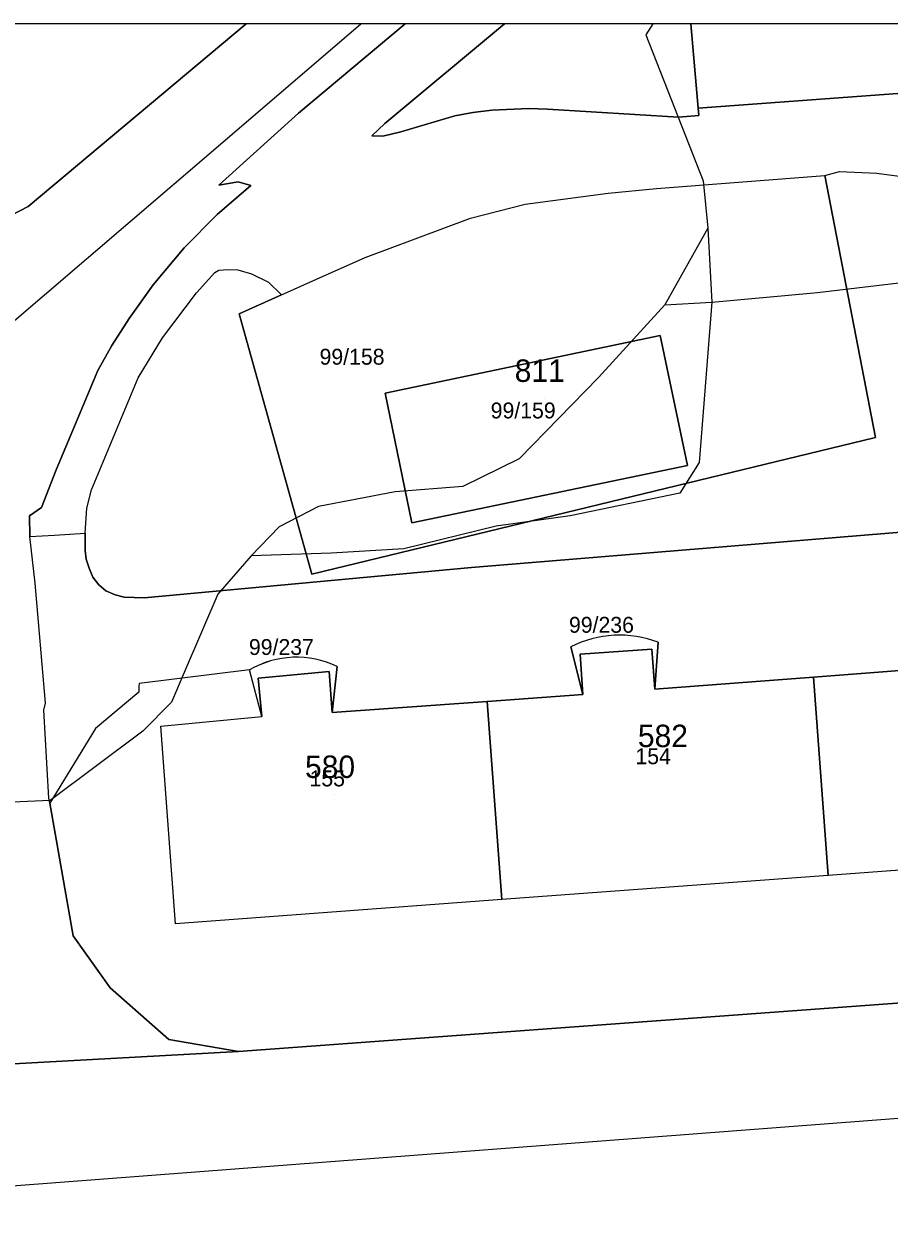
# Model space of a CAD drawing. Extents: x -873642 to -872917, y -1012962 to -1012567.
# Drawn here: x -873481.3 to -873435, y -1012631 to -1012567.5 of the extents above; entities that cross this region are included whole.
import ezdxf

# ---------------------------------------------------------------- set-up
doc = ezdxf.new("R2010")
doc.units = 0
for name, color, linetype in [('adresni_misto', 7, 'Continuous'), ('cisla_parcelni_kn', 7, 'Continuous'), ('cislo_domovni', 7, 'Continuous'), ('osy_ulic', 7, 'Continuous'), ('parcely_kn', 7, 'Continuous'), ('stavebni_objekty_bydleni', 7, 'Continuous'), ('TRASY - zamereno', 7, 'Continuous')]:
    doc.layers.add(name, color=color, linetype=linetype)

msp = doc.modelspace()

# ---------------------------------------------------------------- linework, layer by layer
at = {"layer": 'adresni_misto'}
for p, q in [((-873453.46, -1012587.56), (-873453.46, -1012587.56)), ((-873446.87, -1012607.1), (-873446.87, -1012607.1)), ((-873464.68, -1012608.75), (-873464.68, -1012608.75))]:
    msp.add_line(p, q, dxfattribs=at)
at = {"layer": 'osy_ulic'}
for points in [[(-873484.82, -1012585.93), (-873471.05, -1012574.15), (-873463.295, -1012567.5)], [(-872916.927, -1012586.659), (-872957.62, -1012590.24), (-872977.73, -1012591.46), (-872994.83, -1012592.51), (-873031.96, -1012595.34), (-873059.56, -1012597.3), (-873096.52, -1012600.28), (-873281.07, -1012614.36), (-873481.95, -1012629.68)]]:
    msp.add_lwpolyline(points, dxfattribs=at)
at = {"layer": 'parcely_kn'}
for p, q in [((-873469.424, -1012567.5), (-873497.388, -1012567.5)), ((-873469.424, -1012567.5), (-873497.388, -1012567.5)), ((-873460.925, -1012567.5), (-873469.424, -1012567.5)), ((-873460.925, -1012567.5), (-873469.424, -1012567.5)), ((-873455.607, -1012567.5), (-873460.925, -1012567.5)), ((-873455.607, -1012567.5), (-873460.925, -1012567.5)), ((-873445.635, -1012567.5), (-873455.607, -1012567.5)), ((-873445.635, -1012567.5), (-873455.607, -1012567.5)), ((-873427.436, -1012567.5), (-873445.635, -1012567.5)), ((-873427.436, -1012567.5), (-873445.635, -1012567.5))]:
    msp.add_line(p, q, dxfattribs=at)
for points in [[(-873497.388, -1012567.5), (-873487.83, -1012577.76), (-873484.77, -1012578.86), (-873482.9, -1012578.2), (-873481.1, -1012577.28), (-873469.424, -1012567.5)], [(-873497.388, -1012567.5), (-873487.83, -1012577.76), (-873484.77, -1012578.86), (-873482.9, -1012578.2), (-873481.1, -1012577.28), (-873469.424, -1012567.5)], [(-873491.33, -1012623.66), (-873469.84, -1012622.48), (-873473.56, -1012621.85), (-873476.71, -1012619.07), (-873478.69, -1012616.29), (-873479.94, -1012609.19), (-873479.99, -1012608.93), (-873480.25, -1012604.22), (-873480.17, -1012603.85), (-873480.72, -1012597.42), (-873481, -1012594.94), (-873481.03, -1012593.83), (-873480.38, -1012593.38), (-873479.6, -1012591.37), (-873478.7, -1012589.24), (-873477.36, -1012586.05), (-873476.61, -1012584.71), (-873475.69, -1012583.26), (-873474.41, -1012581.46), (-873472.75, -1012579.49), (-873470.98, -1012577.7), (-873470.59, -1012577.36), (-873469.18, -1012576.16), (-873469.86, -1012575.96), (-873470.89, -1012576.13), (-873466.63, -1012572.29), (-873463.77, -1012569.89), (-873460.925, -1012567.5)], [(-873491.33, -1012623.66), (-873469.84, -1012622.48), (-873473.56, -1012621.85), (-873476.71, -1012619.07), (-873478.69, -1012616.29), (-873479.94, -1012609.19), (-873479.99, -1012608.93), (-873480.25, -1012604.22), (-873480.17, -1012603.85), (-873480.72, -1012597.42), (-873481, -1012594.94), (-873481.03, -1012593.83), (-873480.38, -1012593.38), (-873479.6, -1012591.37), (-873478.7, -1012589.24), (-873477.36, -1012586.05), (-873476.61, -1012584.71), (-873475.69, -1012583.26), (-873474.41, -1012581.46), (-873472.75, -1012579.49), (-873470.98, -1012577.7), (-873470.59, -1012577.36), (-873469.18, -1012576.16), (-873469.86, -1012575.96), (-873470.89, -1012576.13), (-873466.63, -1012572.29), (-873463.77, -1012569.89), (-873460.925, -1012567.5)], [(-873469.424, -1012567.5), (-873481.1, -1012577.28), (-873482.9, -1012578.2)], [(-873469.424, -1012567.5), (-873481.1, -1012577.28), (-873482.9, -1012578.2)], [(-873460.925, -1012567.5), (-873463.77, -1012569.89), (-873466.63, -1012572.29), (-873470.89, -1012576.13), (-873469.86, -1012575.96), (-873469.18, -1012576.16), (-873470.59, -1012577.36), (-873470.98, -1012577.7), (-873472.75, -1012579.49), (-873474.41, -1012581.46), (-873475.69, -1012583.26), (-873476.61, -1012584.71), (-873477.36, -1012586.05), (-873478.7, -1012589.24), (-873479.6, -1012591.37), (-873480.38, -1012593.38), (-873481.03, -1012593.83), (-873481, -1012594.94), (-873479.68, -1012594.86), (-873478.04, -1012594.75), (-873477.96, -1012593.41), (-873477.71, -1012592.43), (-873475.2, -1012586.45), (-873473.91, -1012584.31), (-873472.09, -1012581.89), (-873471.1, -1012580.8), (-873470.89, -1012580.68), (-873470.4, -1012580.64), (-873469.88, -1012580.67), (-873469.15, -1012580.88), (-873468.24, -1012581.32), (-873467.53, -1012582), (-873465.67, -1012581.17), (-873463.07, -1012580), (-873457.43, -1012577.9), (-873454.51, -1012577.15), (-873450.06, -1012576.56), (-873447.47, -1012576.31), (-873438.46, -1012575.62), (-873437.69, -1012575.4), (-873435.68, -1012575.49), (-873433.69, -1012575.76)], [(-873460.925, -1012567.5), (-873463.77, -1012569.89), (-873466.63, -1012572.29), (-873470.89, -1012576.13), (-873469.86, -1012575.96), (-873469.18, -1012576.16), (-873470.59, -1012577.36), (-873470.98, -1012577.7), (-873472.75, -1012579.49), (-873474.41, -1012581.46), (-873475.69, -1012583.26), (-873476.61, -1012584.71), (-873477.36, -1012586.05), (-873478.7, -1012589.24), (-873479.6, -1012591.37), (-873480.38, -1012593.38), (-873481.03, -1012593.83), (-873481, -1012594.94), (-873479.68, -1012594.86), (-873478.04, -1012594.75), (-873477.96, -1012593.41), (-873477.71, -1012592.43), (-873475.2, -1012586.45), (-873473.91, -1012584.31), (-873472.09, -1012581.89), (-873471.1, -1012580.8), (-873470.89, -1012580.68), (-873470.4, -1012580.64), (-873469.88, -1012580.67), (-873469.15, -1012580.88), (-873468.24, -1012581.32), (-873467.53, -1012582), (-873465.67, -1012581.17), (-873463.07, -1012580), (-873457.43, -1012577.9), (-873454.51, -1012577.15), (-873450.06, -1012576.56), (-873447.47, -1012576.31), (-873438.46, -1012575.62), (-873437.69, -1012575.4), (-873435.68, -1012575.49), (-873433.69, -1012575.76)], [(-873427.436, -1012567.5), (-873427.29, -1012570.69), (-873445.24, -1012572.02), (-873445.21, -1012572.41), (-873446.29, -1012572.49), (-873453.3, -1012572.07), (-873454.3, -1012572.03), (-873456.29, -1012572.12), (-873457.3, -1012572.25), (-873458.26, -1012572.43), (-873461.15, -1012573.28), (-873462.12, -1012573.52), (-873462.71, -1012573.49), (-873462.01, -1012572.83), (-873455.607, -1012567.5)], [(-873455.607, -1012567.5), (-873462.01, -1012572.83), (-873462.71, -1012573.49), (-873462.12, -1012573.52), (-873461.15, -1012573.28), (-873458.26, -1012572.43), (-873457.3, -1012572.25), (-873456.29, -1012572.12), (-873454.3, -1012572.03), (-873453.3, -1012572.07), (-873446.29, -1012572.49), (-873445.21, -1012572.41), (-873445.24, -1012572.02), (-873445.635, -1012567.5)], [(-873427.436, -1012567.5), (-873427.29, -1012570.69), (-873445.24, -1012572.02), (-873445.21, -1012572.41), (-873446.29, -1012572.49), (-873453.3, -1012572.07), (-873454.3, -1012572.03), (-873456.29, -1012572.12), (-873457.3, -1012572.25), (-873458.26, -1012572.43), (-873461.15, -1012573.28), (-873462.12, -1012573.52), (-873462.71, -1012573.49), (-873462.01, -1012572.83), (-873455.607, -1012567.5)], [(-873455.607, -1012567.5), (-873462.01, -1012572.83), (-873462.71, -1012573.49), (-873462.12, -1012573.52), (-873461.15, -1012573.28), (-873458.26, -1012572.43), (-873457.3, -1012572.25), (-873456.29, -1012572.12), (-873454.3, -1012572.03), (-873453.3, -1012572.07), (-873446.29, -1012572.49), (-873445.21, -1012572.41), (-873445.24, -1012572.02), (-873445.635, -1012567.5)], [(-873445.635, -1012567.5), (-873445.24, -1012572.02), (-873427.29, -1012570.69), (-873427.436, -1012567.5)], [(-873445.635, -1012567.5), (-873445.24, -1012572.02), (-873427.29, -1012570.69), (-873427.436, -1012567.5)], [(-873430.92, -1012594.41), (-873457.37, -1012596.59), (-873474.88, -1012598.21), (-873475.95, -1012598.18), (-873476.43, -1012598.05), (-873476.93, -1012597.83), (-873477.31, -1012597.51), (-873477.63, -1012597.1), (-873477.83, -1012596.62), (-873477.99, -1012596.15), (-873478.04, -1012595.68), (-873478.04, -1012594.75), (-873477.96, -1012593.41), (-873477.71, -1012592.43), (-873475.2, -1012586.45), (-873473.91, -1012584.31), (-873472.09, -1012581.89), (-873471.1, -1012580.8), (-873470.89, -1012580.68), (-873470.4, -1012580.64), (-873469.88, -1012580.67), (-873469.15, -1012580.88), (-873468.24, -1012581.32), (-873467.53, -1012582), (-873469.8, -1012583.02), (-873465.92, -1012596.95), (-873435.75, -1012589.63), (-873438.46, -1012575.62), (-873437.69, -1012575.4), (-873435.68, -1012575.49), (-873433.69, -1012575.76)], [(-873430.92, -1012594.41), (-873457.37, -1012596.59), (-873474.88, -1012598.21), (-873475.95, -1012598.18), (-873476.43, -1012598.05), (-873476.93, -1012597.83), (-873477.31, -1012597.51), (-873477.63, -1012597.1), (-873477.83, -1012596.62), (-873477.99, -1012596.15), (-873478.04, -1012595.68), (-873478.04, -1012594.75), (-873477.96, -1012593.41), (-873477.71, -1012592.43), (-873475.2, -1012586.45), (-873473.91, -1012584.31), (-873472.09, -1012581.89), (-873471.1, -1012580.8), (-873470.89, -1012580.68), (-873470.4, -1012580.64), (-873469.88, -1012580.67), (-873469.15, -1012580.88), (-873468.24, -1012581.32), (-873467.53, -1012582), (-873469.8, -1012583.02), (-873465.92, -1012596.95), (-873435.75, -1012589.63), (-873438.46, -1012575.62), (-873437.69, -1012575.4), (-873435.68, -1012575.49), (-873433.69, -1012575.76)], [(-873469.25, -1012602.07), (-873475.15, -1012602.79), (-873475.18, -1012602.94), (-873475.17, -1012603.26), (-873477.49, -1012605.2), (-873479.94, -1012609.19), (-873479.99, -1012608.93), (-873480.25, -1012604.22), (-873480.17, -1012603.85), (-873480.72, -1012597.42), (-873481, -1012594.94), (-873479.68, -1012594.86), (-873478.04, -1012594.75), (-873478.04, -1012595.68), (-873477.99, -1012596.15), (-873477.83, -1012596.62), (-873477.63, -1012597.1), (-873477.31, -1012597.51), (-873476.93, -1012597.83), (-873476.43, -1012598.05), (-873475.95, -1012598.18), (-873474.88, -1012598.21), (-873457.37, -1012596.59), (-873430.92, -1012594.41)], [(-873469.25, -1012602.07), (-873475.15, -1012602.79), (-873475.18, -1012602.94), (-873475.17, -1012603.26), (-873477.49, -1012605.2), (-873479.94, -1012609.19), (-873479.99, -1012608.93), (-873480.25, -1012604.22), (-873480.17, -1012603.85), (-873480.72, -1012597.42), (-873481, -1012594.94), (-873479.68, -1012594.86), (-873478.04, -1012594.75), (-873478.04, -1012595.68), (-873477.99, -1012596.15), (-873477.83, -1012596.62), (-873477.63, -1012597.1), (-873477.31, -1012597.51), (-873476.93, -1012597.83), (-873476.43, -1012598.05), (-873475.95, -1012598.18), (-873474.88, -1012598.21), (-873457.37, -1012596.59), (-873430.92, -1012594.41)], [(-873143.44, -1012597.91), (-873216.55, -1012603.73), (-873279.94, -1012608.27), (-873348.3, -1012613.15), (-873406.66, -1012617.85), (-873469.84, -1012622.48), (-873491.33, -1012623.66), (-873566.46, -1012629.92), (-873583.11, -1012630.93), (-873584.28, -1012631.65), (-873606.27, -1012634.41), (-873608.98, -1012633.05), (-873615.37, -1012633.09), (-873642.294, -1012633.957)], [(-873431.45, -1012599.47), (-873430.98, -1012601.84), (-873439.07, -1012602.45), (-873447.57, -1012603.1), (-873447.38, -1012600.59)], [(-873431.45, -1012599.47), (-873430.98, -1012601.84), (-873439.07, -1012602.45), (-873447.57, -1012603.1), (-873447.38, -1012600.59)], [(-873407.04, -1012610.98), (-873418.47, -1012611.57), (-873418.89, -1012601.06), (-873421.55, -1012601.17), (-873420.8, -1012611.77), (-873438.29, -1012613.07), (-873455.75, -1012614.36), (-873473.21, -1012615.66), (-873473.99, -1012605.07), (-873468.6, -1012604.57), (-873469.25, -1012602.07), (-873475.15, -1012602.79), (-873475.18, -1012602.94), (-873475.17, -1012603.26), (-873477.49, -1012605.2), (-873479.94, -1012609.19), (-873478.69, -1012616.29), (-873476.71, -1012619.07), (-873473.56, -1012621.85), (-873469.84, -1012622.48), (-873406.66, -1012617.85)], [(-873407.04, -1012610.98), (-873418.47, -1012611.57), (-873418.89, -1012601.06), (-873421.55, -1012601.17), (-873420.8, -1012611.77), (-873438.29, -1012613.07), (-873455.75, -1012614.36), (-873473.21, -1012615.66), (-873473.99, -1012605.07), (-873468.6, -1012604.57), (-873469.25, -1012602.07), (-873475.15, -1012602.79), (-873475.18, -1012602.94), (-873475.17, -1012603.26), (-873477.49, -1012605.2), (-873479.94, -1012609.19), (-873478.69, -1012616.29), (-873476.71, -1012619.07), (-873473.56, -1012621.85), (-873469.84, -1012622.48), (-873406.66, -1012617.85)], [(-873452.06, -1012600.84), (-873451.41, -1012603.38), (-873456.54, -1012603.75), (-873464.82, -1012604.35), (-873464.56, -1012601.89)], [(-873452.06, -1012600.84), (-873451.41, -1012603.38), (-873456.54, -1012603.75), (-873464.82, -1012604.35), (-873464.56, -1012601.89)], [(-873451.56, -1012601.23), (-873451.41, -1012603.38), (-873452.06, -1012600.84)], [(-873451.56, -1012601.23), (-873451.41, -1012603.38), (-873452.06, -1012600.84)], [(-873447.38, -1012600.59), (-873447.57, -1012603.1), (-873447.73, -1012600.96), (-873451.56, -1012601.23)], [(-873447.38, -1012600.59), (-873447.57, -1012603.1), (-873447.73, -1012600.96), (-873451.56, -1012601.23)], [(-873468.79, -1012602.51), (-873468.6, -1012604.57), (-873469.25, -1012602.07)], [(-873468.79, -1012602.51), (-873468.6, -1012604.57), (-873469.25, -1012602.07)], [(-873464.56, -1012601.89), (-873464.82, -1012604.35), (-873464.98, -1012602.15), (-873468.79, -1012602.51)], [(-873464.56, -1012601.89), (-873464.82, -1012604.35), (-873464.98, -1012602.15), (-873468.79, -1012602.51)]]:
    msp.add_lwpolyline(points, dxfattribs=at)
for points in [[(-873463.07, -1012580), (-873457.43, -1012577.9), (-873454.51, -1012577.15), (-873450.06, -1012576.56), (-873447.47, -1012576.31), (-873438.46, -1012575.62), (-873435.75, -1012589.63), (-873465.92, -1012596.95), (-873469.8, -1012583.02), (-873467.53, -1012582), (-873465.67, -1012581.17)], [(-873463.07, -1012580), (-873457.43, -1012577.9), (-873454.51, -1012577.15), (-873450.06, -1012576.56), (-873447.47, -1012576.31), (-873438.46, -1012575.62), (-873435.75, -1012589.63), (-873465.92, -1012596.95), (-873469.8, -1012583.02), (-873467.53, -1012582), (-873465.67, -1012581.17)], [(-873462, -1012587.26), (-873447.27, -1012584.18), (-873445.82, -1012591.14), (-873460.56, -1012594.2)], [(-873445.82, -1012591.14), (-873447.27, -1012584.18), (-873462, -1012587.26), (-873460.56, -1012594.2)], [(-873462, -1012587.26), (-873447.27, -1012584.18), (-873445.82, -1012591.14), (-873460.56, -1012594.2)], [(-873445.82, -1012591.14), (-873447.27, -1012584.18), (-873462, -1012587.26), (-873460.56, -1012594.2)], [(-873439.07, -1012602.45), (-873430.98, -1012601.84), (-873431.13, -1012599.78), (-873427.15, -1012599.48), (-873427, -1012601.56), (-873421.55, -1012601.17), (-873420.8, -1012611.77), (-873438.29, -1012613.07)], [(-873439.07, -1012602.45), (-873430.98, -1012601.84), (-873431.13, -1012599.78), (-873427.15, -1012599.48), (-873427, -1012601.56), (-873421.55, -1012601.17), (-873420.8, -1012611.77), (-873438.29, -1012613.07)], [(-873456.54, -1012603.75), (-873451.41, -1012603.38), (-873451.56, -1012601.23), (-873447.73, -1012600.96), (-873447.57, -1012603.1), (-873439.07, -1012602.45), (-873438.29, -1012613.07), (-873455.75, -1012614.36)], [(-873456.54, -1012603.75), (-873451.41, -1012603.38), (-873451.56, -1012601.23), (-873447.73, -1012600.96), (-873447.57, -1012603.1), (-873439.07, -1012602.45), (-873438.29, -1012613.07), (-873455.75, -1012614.36)], [(-873464.82, -1012604.35), (-873456.54, -1012603.75), (-873455.75, -1012614.36), (-873473.21, -1012615.66), (-873473.99, -1012605.07), (-873468.6, -1012604.57), (-873468.79, -1012602.51), (-873464.98, -1012602.15)], [(-873464.82, -1012604.35), (-873456.54, -1012603.75), (-873455.75, -1012614.36), (-873473.21, -1012615.66), (-873473.99, -1012605.07), (-873468.6, -1012604.57), (-873468.79, -1012602.51), (-873464.98, -1012602.15)]]:
    msp.add_lwpolyline(points, close=True, dxfattribs=at)
for centre, radius, start, end in [((-873449.44, -1012605.957), 5.749, 69.00091, 117.11462), ((-873449.44, -1012605.957), 5.748, 69.00081, 117.11472), ((-873449.44, -1012605.957), 5.749, 69.00091, 117.11462), ((-873449.44, -1012605.957), 5.748, 69.00081, 117.11472), ((-873466.736, -1012606.388), 4.996, 64.18303, 120.21278), ((-873466.736, -1012606.387), 4.996, 64.18244, 120.21337), ((-873466.736, -1012606.388), 4.996, 64.18303, 120.21278), ((-873466.736, -1012606.387), 4.996, 64.18244, 120.21337)]:
    msp.add_arc(centre, radius, start, end, dxfattribs=at)
at = {"layer": 'stavebni_objekty_bydleni'}
msp.add_line((-873427.436, -1012567.5), (-873445.635, -1012567.5), dxfattribs=at)
msp.add_lwpolyline([(-873445.635, -1012567.5), (-873445.24, -1012572.02), (-873427.29, -1012570.69), (-873427.436, -1012567.5)], dxfattribs=at)
for points in [[(-873462, -1012587.26), (-873447.27, -1012584.18), (-873445.82, -1012591.14), (-873460.56, -1012594.2)], [(-873438.29, -1012613.07), (-873439.07, -1012602.45), (-873430.98, -1012601.84), (-873431.13, -1012599.78), (-873427.15, -1012599.48), (-873427, -1012601.56), (-873421.55, -1012601.17), (-873420.8, -1012611.77)], [(-873455.75, -1012614.36), (-873456.54, -1012603.75), (-873451.41, -1012603.38), (-873451.56, -1012601.23), (-873447.73, -1012600.96), (-873447.57, -1012603.1), (-873439.07, -1012602.45), (-873438.29, -1012613.07)], [(-873473.21, -1012615.66), (-873473.99, -1012605.07), (-873468.6, -1012604.57), (-873468.79, -1012602.51), (-873464.98, -1012602.15), (-873464.82, -1012604.35), (-873456.54, -1012603.75), (-873455.75, -1012614.36)]]:
    msp.add_lwpolyline(points, close=True, dxfattribs=at)
at = {"layer": 'TRASY - zamereno'}
for p, q in [((-873447.674, -1012567.5), (-873448.04, -1012568.09)), ((-873448.04, -1012568.09), (-873444.98, -1012575.91)), ((-873444.98, -1012575.91), (-873444.73, -1012578.44)), ((-873444.73, -1012578.44), (-873447.03, -1012582.54)), ((-873444.73, -1012578.44), (-873444.51, -1012582.4)), ((-873438.86, -1012581.88), (-873432.13, -1012581.07)), ((-873444.51, -1012582.4), (-873438.86, -1012581.88)), ((-873447.03, -1012582.54), (-873450.57, -1012586.43)), ((-873447.03, -1012582.54), (-873444.51, -1012582.4)), ((-873444.51, -1012582.4), (-873445.2, -1012590.97)), ((-873450.57, -1012586.43), (-873454.82, -1012590.78)), ((-873454.82, -1012590.78), (-873457.84, -1012592.26)), ((-873445.2, -1012590.97), (-873446.23, -1012592.62)), ((-873457.84, -1012592.26), (-873461.45, -1012592.55)), ((-873461.45, -1012592.55), (-873465.56, -1012593.32)), ((-873446.23, -1012592.62), (-873452.09, -1012593.82)), ((-873465.56, -1012593.32), (-873467.67, -1012594.42)), ((-873452.09, -1012593.82), (-873456.06, -1012594.38)), ((-873467.67, -1012594.42), (-873469.17, -1012595.96)), ((-873456.06, -1012594.38), (-873460.99, -1012595.6)), ((-873469.17, -1012595.96), (-873470.94, -1012598.02)), ((-873464.88, -1012595.83), (-873469.17, -1012595.96)), ((-873460.99, -1012595.6), (-873464.88, -1012595.83)), ((-873470.94, -1012598.02), (-873472.74, -1012602.21)), ((-873472.74, -1012602.21), (-873473.42, -1012603.8)), ((-873473.42, -1012603.8), (-873474.96, -1012605.34)), ((-873474.96, -1012605.34), (-873479.92, -1012609.06)), ((-873479.92, -1012609.06), (-873486.09, -1012609.34))]:
    msp.add_line(p, q, dxfattribs=at)

# ---------------------------------------------------------------- texts
at = {"layer": 'cisla_parcelni_kn'}
for s, p in [('99/158', (-873465.502, -1012585.738)), ('99/158', (-873465.502, -1012585.738)), ('99/159', (-873456.346, -1012588.613)), ('99/159', (-873456.346, -1012588.613)), ('99/236', (-873452.158, -1012600.081)), ('99/236', (-873452.158, -1012600.081)), ('99/237', (-873469.283, -1012601.269)), ('99/237', (-873469.283, -1012601.269)), ('154', (-873448.602, -1012607.113)), ('154', (-873448.602, -1012607.113)), ('155', (-873466.04, -1012608.3)), ('155', (-873466.04, -1012608.3))]:
    msp.add_text(s, height=0.85, dxfattribs=at).set_placement(p)
at = {"layer": 'cislo_domovni'}
for s, p in [('811', (-873455.06, -1012586.66)), ('582', (-873448.47, -1012606.2)), ('580', (-873466.28, -1012607.85))]:
    msp.add_text(s, height=1.2, dxfattribs=at).set_placement(p)

doc.saveas('drawing.dxf')
